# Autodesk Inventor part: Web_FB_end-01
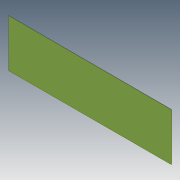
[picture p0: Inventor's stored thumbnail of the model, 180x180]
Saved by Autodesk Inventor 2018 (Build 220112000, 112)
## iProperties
Created: 2018-02
Part Number: Web_FB_end-01
Material: Steel, Mild
Document SubType Name: Modeling
Designer: STK
Density: 7.85 g/cm^3
Appearance: Olive Green
Mass: 492811 g
Surface Area: 129912 cm^2
Volume: 62778.4 cm^3
Author: STK
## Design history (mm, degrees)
sketch "Sketch1"
  geometry: L1 (-2346.325, 1371.6)-(2346.325, 1371.6); L2 (2346.325, 1371.6)-(2346.325, 0); L3 (2346.325, 0)-(-2346.325, 0); L4 (-2346.325, 0)-(-2346.325, 1371.6); L5 (0, 0)-(0, 1371.6)
  constraints: 10 end point, 2 parallel, 2 perpendicular, 1 horizontal, 1 horizontal alignment, 1 midpoint, 1 other
  dimensions: "Height" = 1371.6 distance between parallel lines of L1 L3; "Total_Length" = 4692.65 distance of L1.start L1.end
extrude "Extrusion1" new body sketch "Sketch1" taper "d3" = 0 deg; stored distance "Thickness" = 9.7536
body "Solid1"
